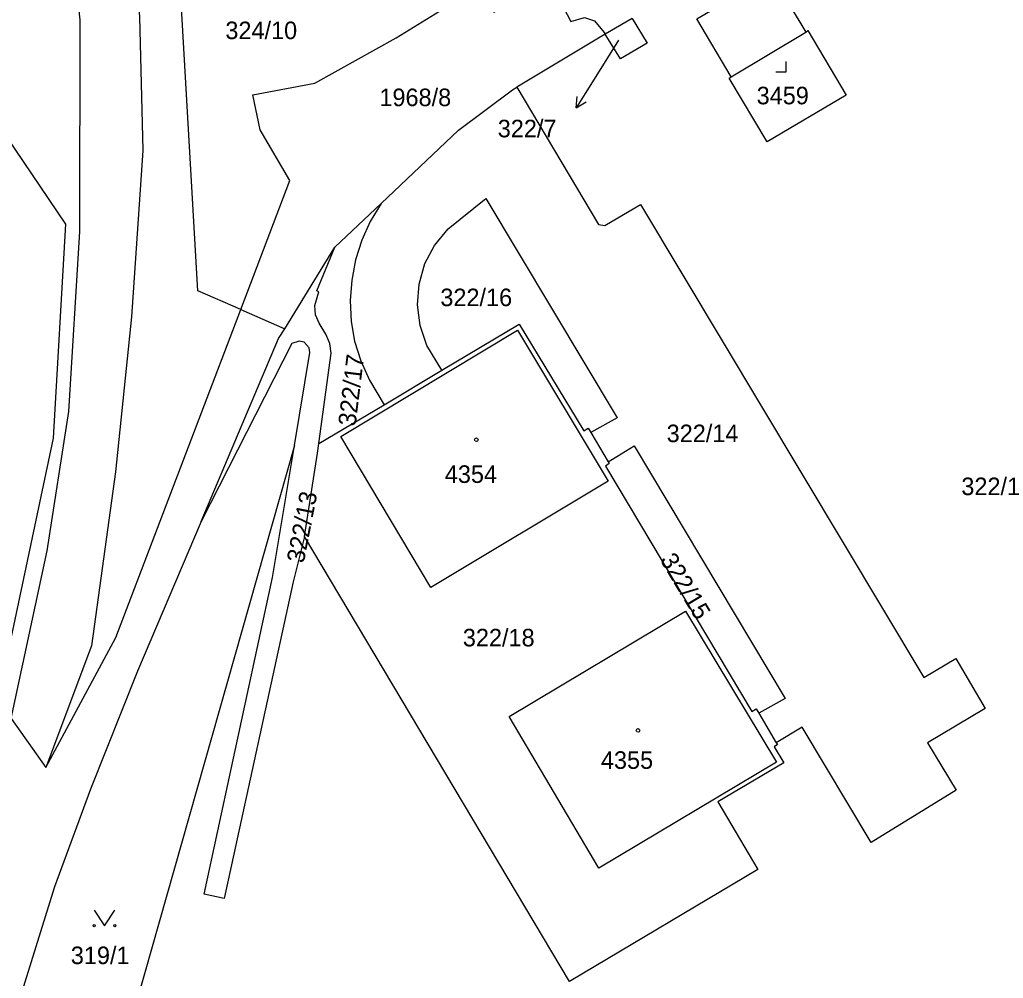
# Model space of a CAD drawing. Extents: x -679220 to -673243, y -1075091 to -1066557.
# Drawn here: x -676063.6 to -675968.3, y -1072555.7 to -1072462.9 of the extents above; entities that cross this region are included whole.
import ezdxf

# ---------------------------------------------------------------- set-up
doc = ezdxf.new("R2010")
doc.units = 0
for name, color, linetype in [('Hranice parcel', 7, 'Continuous'), ('Parcelní čísla', 7, 'Continuous'), ('Pop  PČ popisy', 7, 'Continuous'), ('Vnitřní kresba', 7, 'Continuous'), ('Značky budov', 7, 'Continuous'), ('Značky kultur', 7, 'Continuous')]:
    doc.layers.add(name, color=color, linetype=linetype)

msp = doc.modelspace()

# ---------------------------------------------------------------- linework, layer by layer
at = {"layer": 'Hranice parcel'}
for p, q in [((-676004.29, -1072462.79), (-676006.88, -1072464.32)), ((-676006.88, -1072464.32), (-676015.46, -1072469.44)), ((-676015.46, -1072469.44), (-676007.54, -1072482.75)), ((-676033.07, -1072484.95), (-676028.6, -1072480.72)), ((-676028.6, -1072480.72), (-676029.64, -1072482.44)), ((-676037.93, -1072492.84), (-676033.07, -1072484.95)), ((-676034.82, -1072489.18), (-676033.07, -1072484.95)), ((-676042.19, -1072490.98), (-676037.93, -1072492.84)), ((-676037.24, -1072494.27), (-676046.03, -1072511.49)), ((-676036.99, -1072504.14), (-676035.49, -1072495.15)), ((-676028.3, -1072500.19), (-676022.71, -1072496.84)), ((-676034.62, -1072503.95), (-676028.3, -1072500.19)), ((-676008.27, -1072502.9), (-676006.61, -1072505.73)), ((-676036.99, -1072504.14), (-676064.58, -1072601.42)), ((-676039.11, -1072516.92), (-676036.99, -1072504.14)), ((-675992.01, -1072530.08), (-675990.32, -1072532.93)), ((-676064.43, -1072530.6), (-676061.06, -1072535.34))]:
    msp.add_line(p, q, dxfattribs=at)
for points in [[(-676064.43, -1072530.6), (-676060.93, -1072514.33), (-676058.84, -1072500.85), (-676057.79, -1072483.42), (-676057.73, -1072462.91), (-676058.94, -1072451.8), (-676060.84, -1072444.17), (-676066.6, -1072424.75), (-676080.98, -1072400.72), (-676089.25, -1072390.86), (-676096.74, -1072383.24), (-676106.51, -1072374.56), (-676118.43, -1072364.57)], [(-676084.95, -1072387.22), (-676077.08, -1072395.86), (-676065.96, -1072411.11), (-676061.23, -1072421.61), (-676052.78, -1072452.85), (-676052.01, -1072462.63), (-676051.68, -1072475.56), (-676052.77, -1072491.68), (-676054.32, -1072506.68), (-676056.64, -1072523.56), (-676061.06, -1072535.34)], [(-676042.19, -1072490.98), (-676046.35, -1072489.15), (-676048.88, -1072445.51), (-676044.69, -1072442.45)], [(-676020.83, -1072460.75), (-676020.04, -1072462.04), (-676018.39, -1072460.99), (-676017.68, -1072462.18), (-676012.68, -1072459.15), (-676013.39, -1072457.96), (-676012.53, -1072457.58), (-676011.64, -1072457.55), (-676010.84, -1072457.91), (-676010.53, -1072458.33), (-676010.67, -1072459.3), (-676011.05, -1072459.8), (-676011.64, -1072460.34), (-676010.23, -1072463.09), (-676008.89, -1072462.7), (-676007.94, -1072463.03), (-676006.99, -1072464.14), (-676006.88, -1072464.32)], [(-675991.2, -1072474.75), (-675994.88, -1072468.56), (-675994.68, -1072468.44), (-675998.01, -1072462.83), (-675990.79, -1072458.55), (-675987.45, -1072464.1), (-675987.26, -1072463.96), (-675983.55, -1072470.21), (-675991.2, -1072474.75)], [(-676042.19, -1072490.98), (-676037.42, -1072478.47), (-676040.3, -1072473.56), (-676041.01, -1072470.17), (-676035.02, -1072469.05), (-676027.15, -1072464.67), (-676020.83, -1072460.75)], [(-676004.29, -1072462.79), (-676002.82, -1072465.18), (-676005.42, -1072466.71), (-676006.88, -1072464.32)], [(-676070.69, -1072465.69), (-676059.17, -1072482.71), (-676060.35, -1072503.43), (-676065.77, -1072528.95), (-676076.34, -1072567.38), (-676083.41, -1072584.95), (-676093.32, -1072601.73), (-676100.75, -1072617.65), (-676109.37, -1072640.15)], [(-676028.6, -1072480.72), (-676021.11, -1072473.62), (-676015.88, -1072469.69), (-676015.46, -1072469.44)], [(-676022.71, -1072496.84), (-676024.15, -1072494.45), (-676024.82, -1072492.52), (-676025.06, -1072490.52), (-676024.92, -1072488.51), (-676024.37, -1072486.53), (-676023.43, -1072484.76), (-676022.11, -1072483.17), (-676018.46, -1072480.22), (-676005.73, -1072501.45), (-676008.27, -1072502.9)], [(-676007.54, -1072482.75), (-676006.92, -1072482.85), (-676003.48, -1072480.79), (-675976.03, -1072526.6), (-675972.93, -1072524.76), (-675970.07, -1072529.6), (-675975.66, -1072532.93), (-675972.88, -1072537.54), (-675981.13, -1072542.59), (-675987.8, -1072531.43), (-675990.32, -1072532.93)], [(-676029.64, -1072482.44), (-676030.47, -1072484.25), (-676031.08, -1072486.16), (-676031.44, -1072488.14), (-676031.6, -1072490.1), (-676031.48, -1072492.12), (-676031.16, -1072494.04), (-676030.56, -1072495.95), (-676029.73, -1072497.81), (-676028.3, -1072500.19)], [(-676034.62, -1072503.95), (-676033.44, -1072495.21), (-676033.55, -1072494.27), (-676033.94, -1072493.36), (-676034.61, -1072492.31), (-676034.94, -1072491.48), (-676035.02, -1072490.57), (-676034.63, -1072489.27), (-676034.82, -1072489.18)], [(-676061.06, -1072535.34), (-676054.3, -1072522.75), (-676042.19, -1072490.98)], [(-676046.03, -1072511.49), (-676038.52, -1072493.79), (-676037.93, -1072492.84)], [(-676032.51, -1072503.26), (-676015.38, -1072492.98), (-676006.6, -1072507.61), (-676023.78, -1072517.89), (-676032.51, -1072503.26)], [(-676022.71, -1072496.84), (-676015.21, -1072492.38), (-676008.96, -1072502.72), (-676008.53, -1072502.47), (-676008.27, -1072502.9)], [(-676035.49, -1072495.15), (-676035.56, -1072494.67), (-676036.05, -1072494.13), (-676036.54, -1072494.04), (-676037.24, -1072494.27)], [(-676036.02, -1072512.97), (-676034.74, -1072504.88), (-676034.62, -1072503.95)], [(-676006.61, -1072505.73), (-676004.09, -1072504.19), (-675989.44, -1072528.65), (-675992.01, -1072530.08)], [(-676006.61, -1072505.73), (-676006.51, -1072505.9), (-676006.86, -1072506.16), (-675992.69, -1072529.91), (-675992.26, -1072529.65), (-675992.01, -1072530.08)], [(-676046.03, -1072511.49), (-676052.18, -1072525.99), (-676056.74, -1072537.42), (-676060.22, -1072546.9), (-676065.36, -1072563.37), (-676069.71, -1072575.38), (-676077.66, -1072589.53), (-676083.71, -1072599.1)], [(-676036.02, -1072512.97), (-676037.11, -1072517.35), (-676043.8, -1072548.01), (-676045.75, -1072547.59), (-676039.11, -1072516.92)], [(-675990.32, -1072532.93), (-675990.2, -1072533.11), (-675990.52, -1072533.33), (-675989.59, -1072534.89), (-675995.97, -1072538.64), (-675992.11, -1072545.21), (-676010.35, -1072556.04), (-676036.02, -1072512.97)], [(-676016.19, -1072530.39), (-675999.1, -1072520.18), (-675990.31, -1072534.81), (-676007.5, -1072545.09), (-676016.19, -1072530.39)]]:
    msp.add_lwpolyline(points, dxfattribs=at)
at = {"layer": 'Pop  PČ popisy'}
for p, q in [((-676005.59, -1072464.9), (-676008.11, -1072468.91)), ((-676008.11, -1072468.91), (-676009.7, -1072471.455)), ((-676009.7, -1072471.455), (-676009.594, -1072470.34)), ((-676009.7, -1072471.455), (-676008.745, -1072470.871))]:
    msp.add_line(p, q, dxfattribs=at)
at = {"layer": 'Vnitřní kresba'}
msp.add_line((-675994.68, -1072468.44), (-675987.45, -1072464.1), dxfattribs=at)
at = {"layer": 'Značky budov'}
for centre in [(-676019.367, -1072503.589), (-676003.707, -1072531.739)]:
    msp.add_circle(centre, 0.175, dxfattribs=at)
at = {"layer": 'Značky kultur'}
for p, q in [((-675989.36, -1072467.94), (-675989.36, -1072466.94)), ((-675990.361, -1072467.94), (-675989.36, -1072467.94))]:
    msp.add_line(p, q, dxfattribs=at)
msp.add_lwpolyline([(-676056.38, -1072549.149), (-676055.38, -1072550.65), (-676054.38, -1072549.149)], dxfattribs=at)
for centre in [(-676056.38, -1072550.649), (-676054.38, -1072550.649)]:
    msp.add_circle(centre, 0.1, dxfattribs=at)

# ---------------------------------------------------------------- texts
at = {"layer": 'Parcelní čísla'}
for s, p in [('324/10', (-676043.68, -1072464.79)), ('1968/8', (-676028.76, -1072471.279)), ('3459', (-675992.22, -1072471.1)), ('322/7', (-676017.297, -1072474.298)), ('322/16', (-676022.857, -1072490.65)), ('322/14', (-676000.937, -1072503.82)), ('4354', (-676022.424, -1072507.769)), ('322/1', (-675972.39, -1072508.95)), ('322/18', (-676020.677, -1072523.6)), ('4355', (-676007.304, -1072535.46)), ('319/1', (-676058.65, -1072554.37))]:
    msp.add_text(s, height=1.7, dxfattribs=at).set_placement(p)
for s, rotation, p in [('322/17', 83, (-676031.077, -1072502.331)), ('322/13', 79, (-676036.088, -1072515.607)), ('322/15', 301, (-676001.621, -1072515.203))]:
    msp.add_text(s, height=1.7, rotation=rotation, dxfattribs=at).set_placement(p)

doc.saveas('drawing.dxf')
